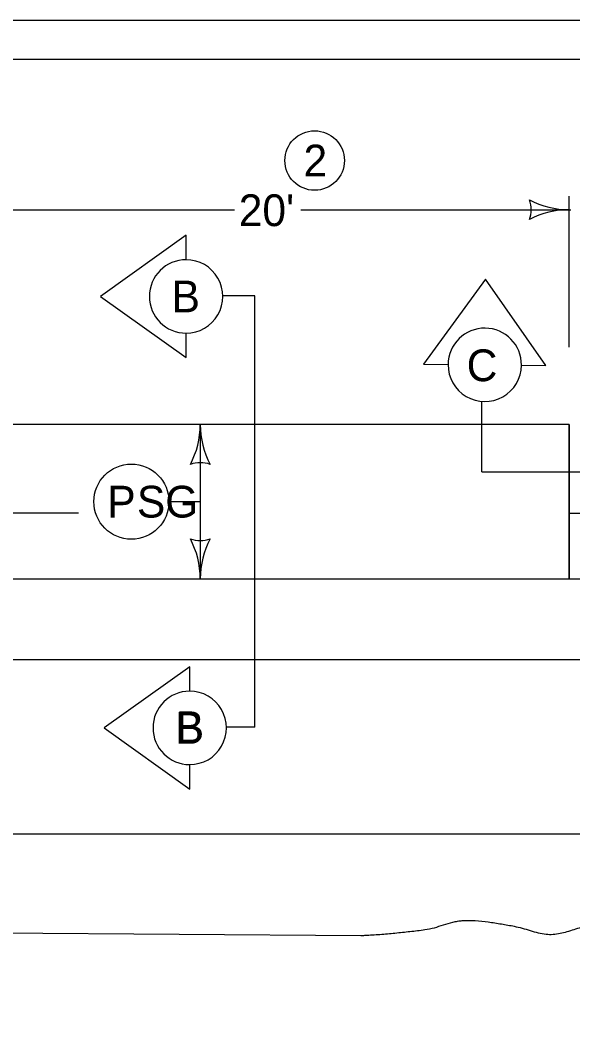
# Model space of a CAD drawing. Extents: x 10133 to 81668, y 5848 to 11018.
# Drawn here: x 11529 to 11807, y 9440 to 9944 of the extents above; entities that cross this region are included whole.
import ezdxf

# ---------------------------------------------------------------- set-up
doc = ezdxf.new("R2010")
doc.units = 0
for name, color, linetype in [('dsnStdLabel', 7, 'Continuous'), ('dsnStdLineWork', 7, 'Continuous'), ('dsnStdPattern', 7, 'Continuous'), ('dsnStdShading', 7, 'Continuous'), ('SheetBorder', 7, 'Continuous'), ('ShtPlotShape', 7, 'Continuous'), ('ShtPlotShapeBatchPrint', 7, 'Continuous')]:
    doc.layers.add(name, color=color, linetype=linetype)

msp = doc.modelspace()

# ---------------------------------------------------------------- linework, layer by layer
at = {"layer": 'dsnStdLabel'}
msp.add_circle((11677.2, 9873.25), 15, dxfattribs=at)
at = {"layer": 'dsnStdLineWork'}
for p, q in [((11805.49, 9740.23), (11500.75, 9740.23)), ((11805.49, 9740.23), (11500.75, 9740.23)), ((11805.49, 9740.23), (11805.49, 9662.65)), ((11805.49, 9662.65), (11805.49, 9740.23)), ((11805.49, 9695.63), (11983.38, 9695.63)), ((10347.65, 9662.65), (11995.12, 9662.65)), ((11500.75, 9662.65), (11805.49, 9662.65)), ((10368.86, 9622), (11982.65, 9622)), ((11371.34, 9485.38), (11700.54, 9482.92))]:
    msp.add_line(p, q, dxfattribs=at)
msp.add_circle((11584.89, 9701.44), 18.93, dxfattribs=at)
msp.add_spline([(11700.54, 9482.92), (11702.54, 9483.03), (11710.11, 9483.51), (11717.68, 9484.17), (11725.23, 9484.98), (11732.76, 9485.88), (11737.51, 9486.88), (11742.19, 9488.32), (11746.86, 9489.68), (11749.21, 9490.17), (11751.58, 9490.44), (11758.12, 9490.43), (11764.71, 9489.77), (11771.29, 9488.74), (11777.81, 9487.59), (11781.82, 9486.65), (11785.79, 9485.45), (11789.77, 9484.32), (11793.78, 9483.6), (11797.32, 9483.57), (11800.87, 9484.07), (11807.98, 9486), (11815.12, 9488.01), (11822.29, 9488.73), (11836.82, 9487.76), (11851.37, 9486.45), (11858.09, 9485.63), (11864.79, 9484.64), (11871.49, 9483.7), (11878.17, 9483.03), (11883.92, 9483.59), (11889.6, 9485.42), (11895.26, 9487.47), (11900.98, 9488.73), (11908.48, 9489.24), (11916.08, 9489.37), (11927.47, 9488.67), (11931.2, 9488.16), (11938.22, 9486.34), (11945.12, 9483.78), (11952.04, 9481.41), (11959.14, 9480.18), (11980.25, 9479.17)], degree=3, dxfattribs=at)
at = {"layer": 'dsnStdPattern'}
for p, q in [((11647.01, 9805.1), (11631.23, 9805.1)), ((11647.01, 9805.1), (11631.23, 9805.1)), ((11647.01, 9587.81), (11647.01, 9805.1)), ((11647.01, 9587.81), (11647.01, 9805.1)), ((11761.44, 9716.47), (11761.44, 9751.91)), ((11761.44, 9716.47), (11761.44, 9751.91)), ((11761.44, 9716.47), (11849.54, 9716.47)), ((11761.44, 9716.47), (11849.54, 9716.47)), ((11647.01, 9587.81), (11633.05, 9587.81)), ((11647.01, 9587.81), (11633.05, 9587.81))]:
    msp.add_line(p, q, dxfattribs=at)
for points in [[(11612.44, 9823.28), (11612.44, 9835.61), (11569.31, 9804.8), (11612.44, 9773.99), (11612.44, 9786.31)], [(11781.41, 9770.18), (11793.73, 9770.07), (11763.32, 9813.48), (11732.11, 9770.63), (11744.44, 9770.52)], [(11614.26, 9606), (11614.26, 9618.32), (11571.13, 9587.51), (11614.26, 9556.7), (11614.26, 9569.02)]]:
    msp.add_lwpolyline(points, dxfattribs=at)
for centre, start, end in [((11612.44, 9804.8), 90.0008, 269.9992), ((11612.44, 9804.8), 269.9992, 90.0008), ((11762.92, 9770.35), 359.4792, 179.4775), ((11762.92, 9770.35), 179.4775, 359.4792), ((11614.26, 9587.51), 90.0008, 269.9992), ((11614.26, 9587.51), 269.9992, 90.0008)]:
    msp.add_arc(centre, 18.49, start, end, dxfattribs=at)
at = {"layer": 'dsnStdShading'}
for p, q in [((11558.3, 9695.63), (10526.39, 9695.63)), ((10352.26, 9534.09), (11994.29, 9534.09))]:
    msp.add_line(p, q, dxfattribs=at)
at = {"layer": 'SheetBorder'}
msp.add_lwpolyline([(10132.52, 9944.02), (13267.53, 9944.02), (13267.53, 7924.02), (10132.52, 7924.02)], close=True, dxfattribs=at)
at = {"layer": 'ShtPlotShape'}
for p, q in [((11805.49, 9779.31), (11805.49, 9855.32)), ((11805.49, 9779.31), (11805.49, 9855.32)), ((11500.75, 9848.49), (11636.75, 9848.49)), ((11500.75, 9848.49), (11636.75, 9848.49)), ((11670.27, 9848.49), (11806.27, 9848.49)), ((11670.27, 9848.49), (11806.27, 9848.49)), ((11619.58, 9740.23), (11619.58, 9662.65)), ((11619.58, 9740.23), (11619.58, 9662.65)), ((11603.82, 9701.44), (11619.58, 9701.44)), ((11603.82, 9701.44), (11619.58, 9701.44))]:
    msp.add_line(p, q, dxfattribs=at)
msp.add_circle((11584.89, 9701.44), 18.93, dxfattribs=at)
msp.add_circle((11584.89, 9701.44), 18.93, dxfattribs=at)
for centre, radius, start, end in [((11769.86, 9848.49), 16.42, 342.2666, 17.7333), ((11805.49, 9890.99), 42.5, 241.9275, 270), ((11769.86, 9848.49), 16.42, 342.2666, 17.7333), ((11805.49, 9890.99), 42.5, 241.9275, 270), ((11805.49, 9805.99), 42.5, 90, 118.0725), ((11805.49, 9805.99), 42.5, 90, 118.0725), ((11577.08, 9740.23), 42.5, 331.9275, 0), ((11577.08, 9740.23), 42.5, 331.9275, 0), ((11662.08, 9740.23), 42.5, 180, 208.0725), ((11662.08, 9740.23), 42.5, 180, 208.0725), ((11619.58, 9704.6), 16.42, 72.2666, 107.7334), ((11619.58, 9704.6), 16.42, 72.2666, 107.7334), ((11619.58, 9698.29), 16.42, 252.2666, 287.7333), ((11577.08, 9662.65), 42.5, 360, 28.0725), ((11619.58, 9698.29), 16.42, 252.2666, 287.7333), ((11577.08, 9662.65), 42.5, 360, 28.0725), ((11662.08, 9662.65), 42.5, 151.9275, 180), ((11662.08, 9662.65), 42.5, 151.9275, 180)]:
    msp.add_arc(centre, radius, start, end, dxfattribs=at)
at = {"layer": 'ShtPlotShapeBatchPrint'}
msp.add_line((10152.18, 9924.36), (13247.87, 9924.36), dxfattribs=at)

# ---------------------------------------------------------------- texts
at = {"layer": 'dsnStdLabel'}
msp.add_text('2', height=16, dxfattribs=at).set_placement((11671.62, 9865.25))
at = {"layer": 'dsnStdPattern'}
for s, p in [('B', (11605.17, 9796.8)), ('B', (11605.17, 9796.8)), ('C', (11753.81, 9762.12)), ('C', (11753.81, 9762.12)), ('B', (11606.99, 9579.51)), ('B', (11606.99, 9579.51)), ('B', (11607.26, 9579.81)), ('B', (11607.26, 9579.81))]:
    msp.add_text(s, height=16, dxfattribs=at).set_placement(p)
at = {"layer": 'ShtPlotShape'}
for s, p in [("20'", (11638.99, 9840.22)), ("20'", (11638.99, 9840.22)), ('SG', (11587.68, 9693.44)), ('SG', (11587.68, 9693.44)), ('P', (11572.76, 9693.44)), ('P', (11572.76, 9693.44))]:
    msp.add_text(s, height=16, dxfattribs=at).set_placement(p)

doc.saveas('drawing.dxf')
